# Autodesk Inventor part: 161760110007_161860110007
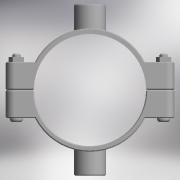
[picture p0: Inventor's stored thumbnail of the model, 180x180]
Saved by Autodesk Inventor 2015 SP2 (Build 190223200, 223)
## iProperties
Created: 2017-05
Part Number: 161760110007_161860110007
Material: Generic
Description: PLASSON DOUBLE SADDLE 110-3/4"
Document SubType Name: Modeling
Designer: KIM
Density: 1 g/cm^3
Appearance: Default
Author: KIM
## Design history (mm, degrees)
derived "16176.ipt"
feature "Solid1::16176.ipt"
feature "Solid2::16176.ipt"
tag "TaggingFeature1"
body "Solid1"
body "Solid2"
other parameters: "d0" = 121, "d1" = 165, "d2" = 55, "d4" = 116, "d5" = 0, "d6" = 8.25, "d7" = 165, "d8" = 0.1, "d10" = 0, "d11" = 1.1, "d20" = 1.1, "d23" = 1.1, "d36" = 13, "d37" = 10.4, "d38" = 63, "d39" = 0, "d40" = 3, "d41" = 5, "d42" = 0, "d43" = 8, "d44" = 3, "d45" = 0, "d46" = 1.1, "d52" = 24.117, "d53" = 19, "d54" = 0, "d57" = 0, "d58" = 118.8, "d60" = 0, "d62" = 13, "d63" = 10.4, "d66" = 95.2, "d67" = 168, "d68" = 31.3521, "d69" = 24.117, "d70" = 19, "d71" = 0, "d74" = 0, "d75" = 1.1, "G_" = 24.117, "A_" = 84, "L_" = 165, "L_1" = 116, "l_2" = 19
